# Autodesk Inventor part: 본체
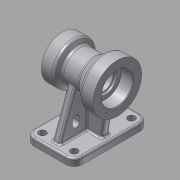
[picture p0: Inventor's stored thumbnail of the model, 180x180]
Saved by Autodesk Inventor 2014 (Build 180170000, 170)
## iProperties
Created: 2015-08
Part Number: 본체
Material: 알루미늄 6061
Document SubType Name: Modeling
Designer: USER
Density: 2.71 g/cm^3
Appearance: 알루미늄 - 평지
Mass: 1062.79 g
Surface Area: 749.652 cm^2
Volume: 392.172 cm^3
Author: USER
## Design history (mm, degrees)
sketch "스케치1"
  geometry: L1 (-40, -61)-(40, -61); L2 (40, -61)-(40, 61); L3 (40, 61)-(-40, 61); L4 (-40, 61)-(-40, -61); 3 further points
  constraints: 8 end point, 2 midpoint, 2 parallel, 1 horizontal, 1 horizontal alignment, 1 perpendicular, 1 vertical alignment
  dimensions: "d0" = 122 distance of L3.end L1.start; "d1" = 80 distance of L1.start L1.end
extrude "돌출1" new body sketch "스케치1" distance "d2" = 12; taper "d3" = 0 deg
sketch "스케치2"
  geometry: L1 (40, 0)-(-40, 0) reference; L2 (-40, 0)-(-40, 12) reference; L3 (40, 12)-(-40, 12) reference; L4 (40, 0)-(40, 12) reference; L5 (-50, 90)-(-50, 130); L6 (-50, 130)-(-30, 130); L7 (-30, 130)-(-13.315, 116); L8 (-13.315, 116)-(14.804, 116); L9 (14.804, 116)-(20, 125); L10 (20, 125)-(40, 125); L11 (40, 125)-(40, 90); L12 (-50, 90)-(40, 90); 1 further point
  constraints: 16 end point, 5 parallel, 2 perpendicular, 1 midpoint, 1 vertical alignment
  dimensions: "d4" = 90 distance between parallel lines of L11 L5; "d5" = 20 distance of L5.end L6.end; "d6" = 20 distance of L9.end L10.end; "d7" = 40 deg angle of L8 L7; "d8" = 60 deg angle of L9 L8; "d15" = 70 diameter of L10 L12; "d16" = 80 diameter of L6 L12; "d17" = 90 distance between parallel lines of L1 L12; "d18" = 52 diameter of L8 L12
revolve "회전1" sketch "스케치2" stored, may be unused: angle "d19" = 90 deg
sketch "스케치3"
  geometry: L1 (61, 12)-(-61, 12) reference; L2 (61, 0)-(61, 12) reference; L3 (-61, 0)-(-61, 12) reference; L4 (-51, 12)-(-29.478, 71.131); L5 (51, 12)-(29.478, 71.131); L6 (-29.478, 71.131)-(-25.091, 83.185); L7 (29.478, 71.131)-(25.091, 83.185); A1 r 35 centre (0, 90) between (-29.478, 71.131) and (29.478, 71.131) reference; A2 r 26 centre (0, 90) between (-25.091, 83.185) and (25.091, 83.185) reference; 1 further point
  constraints: 8 end point, 4 point on circle, 2 collinear, 2 point on line
  dimensions: "d22" = 10 distance from line of L2 L5.start; "d23" = 10 distance from line of L3 L4.start; "d24" = 70 deg angle of L1 L4; "d25" = 70 deg angle of L1 L5
extrude "돌출2" join sketch "스케치3" stored distance "d26" = 12; taper "d27" = 0 deg
sketch "스케치4"
  geometry: L1 (-50, 50)-(-50, 130) reference; L2 (-30, 50)-(-30, 130) reference; L3 (-30, 50)-(-30, 130) reference; L4 (-13.315, 64)-(-13.315, 116) reference; L5 (6, 83.185)-(6, 83.185) reference; L6 (6, 83.185)-(-6, 83.185) reference; L7 (-6, 83.185)-(-6, 83.185) reference; L8 (-6, 83.185)-(6, 83.185) reference; L9 (-13.315, 64)-(-13.315, 116) reference; L10 (14.804, 64)-(14.804, 116) reference; L11 (20, 55)-(20, 125) reference; L12 (40, 55)-(40, 125) reference; L13 (-6, 83.185)-(-6, 12) reference; L14 (6, 83.185)-(-6, 83.185) reference; L15 (6, 12)-(6, 83.185) reference; L16 (-6, 12)-(6, 12) reference; L17 (40, 0)-(-40, 0) reference; L18 (-40, 0)-(-40, 12) reference; L19 (40, 12)-(-40, 12) reference; L20 (40, 0)-(40, 12) reference; L21 (-30, 12)-(-36.7, 50); L22 (-50, 50)-(-30, 50) reference; 1 further point
  constraints: 2 end point, 2 point on line
  dimensions: "d28" = 80 deg angle of L19 L21; "d29" = 10 distance of L21.start L18.end
feature "리브1" sketch "스케치4" dims "d30" = 1, "d31" = 12, "d32" = 0, "d33" = 0, "d34" = 1, "d35" = 1
sketch "스케치5"
  geometry: L1 (-40, 0)-(40, 0) reference; L2 (40, 0)-(40, 12) reference; L3 (-40, 12)-(40, 12) reference; L4 (-40, 0)-(-40, 12) reference; L5 (20, 55)-(20, 125) reference; L6 (40, 55)-(40, 125) reference; L7 (30, 12)-(30, 55); L8 (20, 55)-(40, 55) reference; 1 further point
  constraints: 2 end point, 1 midpoint, 1 parallel, 1 point on line
  dimensions: "d36" = 10 distance between parallel lines of L2 L7
feature "리브2" sketch "스케치5" dims "d37" = 1, "d38" = 12, "d39" = 0, "d40" = 0, "d41" = 1, "d42" = 1
sketch "스케치6"
  geometry: L1 (-12, -6)-(-64.702, -6) reference; L2 (-30, -24)-(-36, -24); L3 (-30, -30)-(-36, -30); L4 (-36, -18)-(-30, -18); L5 (-30, 24)-(-36, 24); L6 (-30, 18)-(-36, 18); L7 (-36, 30)-(-30, 30); L8 (0, 61)-(0, -61) reference; L9 (-33, -24)-(-33, 24); A1 r 6 centre (-30, -24) between (-30, -30) and (-30, -18); A2 r 6 centre (-36, -24) between (-36, -18) and (-36, -30); A3 r 6 centre (-30, 24) between (-30, 18) and (-30, 30); A4 r 6 centre (-36, 24) between (-36, 30) and (-36, 18); 3 further points
  constraints: 18 end point, 8 point on circle, 8 tangent, 5 parallel, 4 centre point, 4 midpoint, 1 horizontal alignment, 1 vertical alignment
  dimensions: "d43" = 12 distance between parallel lines of L3 L4; "d44" = 18 dimension on A1 A2; "d45" = 12 distance between parallel lines of L6 L7; "d46" = 18 dimension on A3 A4; "d47" = 48 distance from line of L5 L2.start; "d48" = 30 distance from line of L8 L3.start
extrude "돌출3" cut sketch "스케치6" distance "d49" = 12; taper "d50" = 0 deg
fillet "모깎기1" dims "d51" = 14
sketch "스케치7"
  geometry: A1 r 14 centre (-26, 47) between (-26, 61) and (-40, 47) reference; A2 r 14 centre (-26, -47) between (-40, -47) and (-26, -61) reference; A3 r 14 centre (26, -47) between (26, -61) and (40, -47) reference; A4 r 14 centre (26, 47) between (40, 47) and (26, 61) reference; 5 further points
  constraints: 4 coincident
hole "구멍1" sketch "스케치7" at (-26, 47), (26, 47), (26, -47), (-26, -47) diameter "d52" = 12; stored, may be unused: countersink angle "d56" = 90 deg, drill point angle "d58" = 118 deg; dims "d53" = 6, "d54" = 4, "d55" = 2, "d57" = 20
fillet "모깎기2" dims "d59" = 3
sketch "스케치8"
  geometry: C1 r 40 at (0, 0) reference; 2 further points
  constraints: 1 coincident
hole "구멍2" sketch "스케치8" at (0, 0) diameter "d62" = 32; stored, may be unused: countersink angle "d66" = 90 deg, drill point angle "d68" = 118 deg; dims "d63" = 6, "d64" = 52, "d65" = 20, "d67" = 50
sketch "스케치9"
  geometry: C1 r 35 at (0, 0) reference; 2 further points
  constraints: 1 coincident
hole "구멍3" sketch "스케치9" at (0, 0) diameter "d69" = 32; stored, may be unused: countersink angle "d73" = 90 deg, drill point angle "d75" = 118 deg; dims "d70" = 6, "d71" = 40, "d72" = 17, "d74" = 50
sketch "스케치10" dims "d76" = 54
  geometry: C1 r 20 at (0, 0) reference; C2 r 35 at (0, 0) reference; 3 further points
  constraints: 2 horizontal alignment, 1 coincident, 2 other
hole "구멍4" sketch "스케치10" at (27, 0) diameter "d77" = 3.242; stored, may be unused: countersink angle "d81" = 90 deg, drill point angle "d83" = 118 deg; dims "d78" = 10, "d79" = 40, "d80" = 17, "d82" = 13
sketch "스케치11" dims "d87" = 66
  geometry: C1 r 26 at (0, 0) reference; C2 r 40 at (0, 0) reference; 3 further points
  constraints: 2 horizontal alignment, 1 coincident, 2 other
hole "구멍5" sketch "스케치11" at (-33, 0) diameter "d88" = 3.242; stored, may be unused: countersink angle "d92" = 90 deg, drill point angle "d94" = 118 deg; dims "d89" = 10, "d90" = 40, "d91" = 17, "d93" = 13
sketch "스케치12"
  geometry: L1 (-10, 0)-(1, 0) reference; L2 (-3, 43.129)-(-3, 0) reference; 3 further points
  constraints: 1 other
  dimensions: "d98" = 24 distance from line of L1 point (13, 24); "d99" = 16 distance from line of L2 point (13, 24)
feature "엠보싱1" sketch "스케치12" dims "d0" = 122, "d1" = 80, "d18" = 52, "d100" = 0.5, "d101" = 0
fillet "모깎기5" dims "d102" = 5
fillet "모깎기6" dims "d103" = 3
sketch "스케치13"
  geometry: C1 r 40 at (0, 0) reference; 2 further points
  constraints: 1 coincident
hole "구멍6" sketch "스케치13" at (0, 0) diameter "d104" = 38; stored, may be unused: countersink angle "d108" = 90 deg, drill point angle "d110" = 0 deg; dims "d105" = 10, "d106" = 40, "d107" = 17, "d109" = 23
fillet "모깎기7" dims "d111" = 3
fillet "모깎기8" dims "d112" = 0.3
chamfer "모따기1" distance "d113" = 1; stored, may be unused: second distance "d114" = 2, angle "d115" = 45 deg
fillet "모깎기9" dims "d116" = 3
node "솔리드1"
pattern_circular "원형 패턴1" dims angle "d85" = 360 deg
pattern_circular "원형 패턴2" dims angle "d96" = 360 deg
node "투영된 루프1"
node "투영된 루프2"
node "투영된 루프3"
node "투영된 루프4"
node "투영된 루프5"
node "투영된 루프6"
node "투영된 루프7"
node "투영된 루프8"
node "투영된 루프9"
node "투영된 루프10"
other parameters: "d20" = 70 deg, "d21" = 70 deg
